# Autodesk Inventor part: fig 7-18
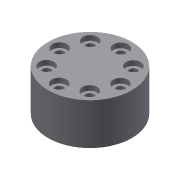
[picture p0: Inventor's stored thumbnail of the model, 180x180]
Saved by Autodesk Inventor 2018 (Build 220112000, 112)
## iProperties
Created: 2004-05
Part Number: fig 7-18
Document SubType Name: Modeling
Designer: CADCIM Technologies
Manufacturer: Standard
Standards Organization: Custom
Density: 1 g/cm^3
Material: Generic
Appearance: Default
Author: CADCIM Technologies
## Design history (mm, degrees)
sketch "Sketch1"
  geometry: C1 r 17.175 at (0, 0)
  constraints: 1 centre point
extrude "Extrusion1" new body sketch "Sketch1" distance "d0" = 17; taper "d1" = 0 deg
sketch "Sketch2"
  geometry: 1 further point
hole "Hole1" sketch "Sketch2" at (12.571, -0.074) diameter "d2" = 3.5; stored, may be unused: countersink angle "d6" = 90 deg, drill point angle "d8" = 118 deg; dims "d3" = 6, "d4" = 6, "d5" = 2, "d7" = 8
pattern_circular "Circular Pattern1" dims angle "d11" = 360 deg
body "Solid1"
